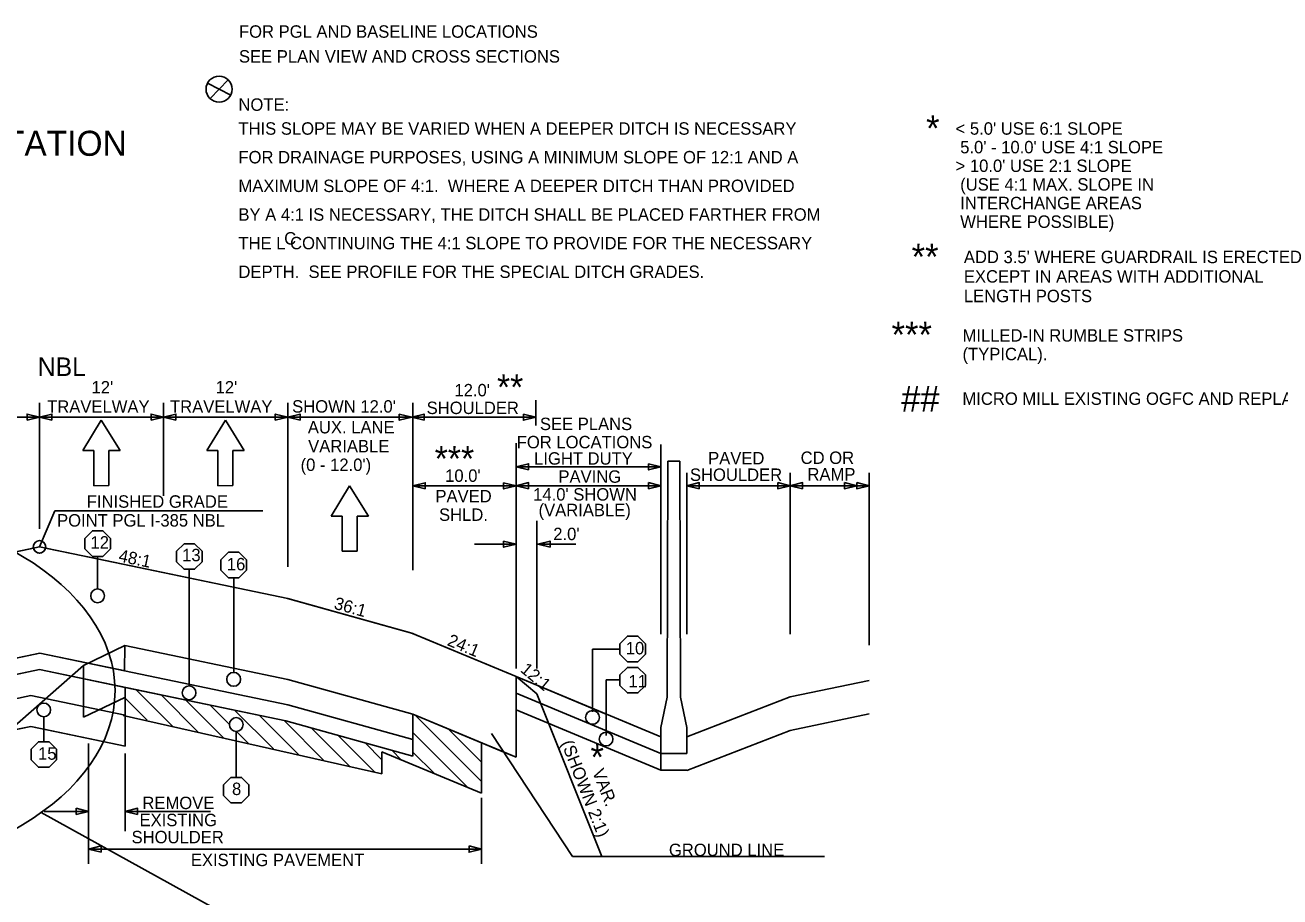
# Model space of a CAD drawing. Extents: x 4832 to 5477, y 4935 to 5220.
# Drawn here: x 5211.3 to 5332.6, y 5131.6 to 5215.9 of the extents above; entities that cross this region are included whole.
import ezdxf

# ---------------------------------------------------------------- set-up
doc = ezdxf.new("R2010")
doc.units = 0
for name, color, linetype in [('CLS_Clear_Zone', 7, 'Continuous'), ('Level 2', 7, 'Continuous'), ('RD_QTY_Milling', 7, 'Continuous'), ('RD_QTY_Miscl_1', 7, 'Continuous'), ('RD_QTY_Surf_Course', 7, 'Continuous'), ('RD_SHT_TX', 7, 'Continuous'), ('RD_SHT_Typical', 7, 'Continuous'), ('RD_TX_Misc1', 7, 'Continuous'), ('RD_TX_TypSect', 7, 'Continuous'), ('RD_XS_ExGround', 7, 'Continuous'), ('RD_XS_ExPaveRet', 7, 'Continuous'), ('RD_XS_PaveShd', 7, 'Continuous'), ('TERMINATOR', 7, 'Continuous'), ('typical_on', 7, 'Continuous')]:
    doc.layers.add(name, color=color, linetype=linetype)

# ---------------------------------------------------------------- blocks, each defined once
blk = doc.blocks.new('AH')
at = {"layer": 'TERMINATOR'}
blk.add_lwpolyline([(-6, 1.5), (0, 0), (-6, -1.5)], close=True, dxfattribs=at)

msp = doc.modelspace()

# ---------------------------------------------------------------- linework, layer by layer
at = {"layer": 'CLS_Clear_Zone'}
msp.add_line((5248.78, 5149.27), (5248.78, 5145.21), dxfattribs=at)
at = {"layer": 'Level 2'}
for p, q in [((5273.37, 5150.93), (5273.45, 5173.73)), ((5274.59, 5173.73), (5273.45, 5173.73)), ((5274.67, 5150.93), (5274.59, 5173.73)), ((5273.37, 5150.93), (5272.77, 5147.97)), ((5275.27, 5147.97), (5274.67, 5150.93)), ((5272.77, 5147.97), (5272.77, 5145.46)), ((5275.27, 5145.46), (5275.27, 5147.97)), ((5272.77, 5145.46), (5275.27, 5145.46)), ((5272.77, 5143.86), (5275.27, 5143.86))]:
    msp.add_line(p, q, dxfattribs=at)
at = {"layer": 'RD_QTY_Milling'}
for p, q in [((5220.95, 5155.91), (5220.91, 5153.45)), ((5236.69, 5152.63), (5220.95, 5155.91)), ((5220.91, 5153.45), (5236.69, 5150.16)), ((5248.78, 5149.27), (5236.69, 5152.63)), ((5258.77, 5152.9), (5258.77, 5151.3)), ((5258.77, 5151.3), (5258.77, 5149.69)), ((5272.77, 5145.46), (5258.77, 5151.3)), ((5258.77, 5151.3), (5272.77, 5145.46)), ((5236.69, 5150.16), (5248.78, 5146.81)), ((5248.78, 5146.81), (5248.78, 5149.27)), ((5258.77, 5149.69), (5272.77, 5143.86)), ((5267.48, 5149.21), (5267.48, 5149.28)), ((5272.77, 5147.07), (5267.5, 5149.27)), ((5272.77, 5145.46), (5272.77, 5147.07)), ((5272.77, 5143.86), (5272.77, 5145.46))]:
    msp.add_line(p, q, dxfattribs=at)
for points in [[(5267.48, 5149.28), (5266.14, 5149.83), (5258.77, 5152.9)], [(5267.5, 5149.27), (5267.48, 5149.21)]]:
    msp.add_lwpolyline(points, dxfattribs=at)
msp.add_circle((5231.47, 5152.64), 0.666, dxfattribs=at)
at = {"layer": 'RD_QTY_Miscl_1'}
for p, q in [((5212.74, 5155.17), (5200.74, 5152.67)), ((5220.91, 5153.45), (5212.74, 5155.17)), ((5200.79, 5151.1), (5212.69, 5153.58)), ((5212.69, 5153.58), (5200.79, 5151.1)), ((5220.99, 5151.85), (5212.69, 5153.58)), ((5236.69, 5150.16), (5220.91, 5153.45)), ((5220.99, 5149.17), (5220.99, 5151.85)), ((5200.79, 5148.76), (5211.87, 5151.07)), ((5211.87, 5151.07), (5200.79, 5148.76)), ((5211.87, 5151.07), (5220.99, 5149.17)), ((5220.99, 5149.17), (5211.87, 5151.07)), ((5248.78, 5146.81), (5236.69, 5150.16)), ((5220.99, 5146.19), (5220.99, 5149.17)), ((5236.5, 5148.62), (5248.78, 5145.21)), ((5248.78, 5145.21), (5248.78, 5146.81))]:
    msp.add_line(p, q, dxfattribs=at)
for points in [[(5212.69, 5153.58), (5220.99, 5151.85), (5236.5, 5148.62)], [(5200.79, 5145.79), (5209.76, 5147.66), (5211.87, 5148.09)], [(5211.87, 5148.09), (5213.11, 5147.83), (5220.99, 5146.19)]]:
    msp.add_lwpolyline(points, dxfattribs=at)
for centre in [(5227.16, 5151.34), (5213.11, 5149.68)]:
    msp.add_circle(centre, 0.666, dxfattribs=at)
at = {"layer": 'RD_QTY_Surf_Course'}
msp.add_line((5292.9, 5152.53), (5285.26, 5150.94), dxfattribs=at)
at = {"layer": 'RD_SHT_Typical'}
for p, q in [((5236.68, 5160.44), (5248.78, 5157.08)), ((5236.69, 5152.63), (5248.78, 5149.27)), ((5258.77, 5151.3), (5258.77, 5152.9)), ((5258.77, 5152.9), (5260.77, 5151.24)), ((5258.77, 5149.69), (5258.77, 5151.3)), ((5236.69, 5150.16), (5248.78, 5146.81)), ((5248.78, 5149.27), (5258.77, 5145.11)), ((5258.77, 5149.69), (5258.77, 5145.11)), ((5292.9, 5149.31), (5285.26, 5147.71)), ((5236.5, 5148.62), (5248.78, 5145.21)), ((5272.77, 5145.46), (5272.77, 5143.86))]:
    msp.add_line(p, q, dxfattribs=at)
at = {"layer": 'RD_TX_Misc1'}
for p, q in [((5218.67, 5177.67), (5216.89, 5174.75)), ((5220.5, 5174.76), (5218.67, 5177.67)), ((5230.67, 5177.67), (5228.89, 5174.75)), ((5232.49, 5174.76), (5230.67, 5177.67)), ((5217.95, 5174.75), (5216.89, 5174.75)), ((5217.95, 5174.75), (5217.95, 5171.35)), ((5219.4, 5174.76), (5220.5, 5174.76)), ((5219.4, 5174.76), (5219.4, 5171.36)), ((5229.94, 5174.75), (5228.89, 5174.75)), ((5229.94, 5174.75), (5229.94, 5171.35)), ((5231.4, 5174.76), (5232.49, 5174.76)), ((5231.4, 5174.76), (5231.4, 5171.36)), ((5219.4, 5171.36), (5217.95, 5171.35)), ((5231.4, 5171.36), (5229.94, 5171.35)), ((5242.67, 5171.34), (5240.89, 5168.41)), ((5244.5, 5168.42), (5242.67, 5171.34)), ((5241.95, 5168.41), (5240.89, 5168.41)), ((5241.95, 5168.41), (5241.95, 5165.01)), ((5243.4, 5168.42), (5244.5, 5168.42)), ((5243.4, 5168.42), (5243.4, 5165.01)), ((5243.4, 5165.01), (5241.95, 5165.01))]:
    msp.add_line(p, q, dxfattribs=at)
at = {"layer": 'RD_TX_TypSect'}
for p, q in [((5229.19, 5208.77), (5230.93, 5210.55)), ((5228.93, 5210.23), (5231.19, 5209.08)), ((5212.7, 5167.18), (5212.7, 5179.34)), ((5224.69, 5170.38), (5224.69, 5179.34)), ((5236.69, 5163.52), (5236.69, 5179.34)), ((5248.78, 5163.2), (5248.78, 5179.34)), ((5260.68, 5177.16), (5260.68, 5179.62)), ((5200.7, 5177.97), (5212.7, 5177.97)), ((5212.7, 5177.97), (5224.69, 5177.97)), ((5224.69, 5177.97), (5236.69, 5177.97)), ((5236.69, 5177.97), (5248.68, 5177.97)), ((5248.68, 5177.97), (5260.68, 5177.97)), ((5258.77, 5153.69), (5258.77, 5175.46)), ((5272.77, 5157.01), (5272.77, 5175.33)), ((5272.77, 5173.17), (5258.77, 5173.17)), ((5275.27, 5157.01), (5275.27, 5172.58)), ((5285.26, 5157.01), (5285.26, 5172.58)), ((5292.9, 5155.95), (5292.9, 5172.58)), ((5248.78, 5171.33), (5258.76, 5171.33)), ((5258.77, 5171.35), (5272.77, 5171.35)), ((5275.27, 5171.35), (5285.26, 5171.35)), ((5285.26, 5171.35), (5292.9, 5171.35)), ((5214.19, 5168.91), (5212.7, 5165.44)), ((5214.19, 5168.91), (5234.3, 5168.91)), ((5260.77, 5153.69), (5260.77, 5167.96)), ((5254.76, 5165.7), (5258.76, 5165.7)), ((5264.53, 5165.7), (5260.86, 5165.7)), ((5200.7, 5162.94), (5212.7, 5165.44)), ((5212.11, 5165.32), (5200.7, 5162.94)), ((5236.69, 5160.44), (5212.7, 5165.44)), ((5218.32, 5161.38), (5218.32, 5164.52)), ((5227.18, 5163.27), (5227.18, 5152.01)), ((5231.47, 5162.46), (5231.47, 5153.31)), ((5248.68, 5157.11), (5236.69, 5160.44)), ((5200.74, 5152.67), (5212.74, 5155.17)), ((5200.74, 5152.67), (5212.74, 5155.17)), ((5220.98, 5153.45), (5212.74, 5155.17)), ((5212.74, 5155.17), (5220.91, 5153.45)), ((5220.95, 5155.91), (5220.91, 5153.45)), ((5220.91, 5153.45), (5220.95, 5155.91)), ((5236.69, 5152.63), (5220.95, 5155.91)), ((5220.95, 5155.91), (5236.69, 5152.63)), ((5268.81, 5155.55), (5266.14, 5155.55)), ((5266.14, 5149.49), (5266.14, 5155.55)), ((5200.79, 5151.1), (5212.69, 5153.58)), ((5236.5, 5148.62), (5212.69, 5153.58)), ((5236.69, 5150.16), (5220.91, 5153.45)), ((5236.69, 5152.63), (5248.78, 5149.27)), ((5258.77, 5151.3), (5258.77, 5152.9)), ((5268.81, 5152.58), (5267.48, 5152.58)), ((5267.48, 5147.2), (5267.48, 5152.58)), ((5220.99, 5149.17), (5220.99, 5151.85)), ((5258.77, 5149.69), (5258.77, 5151.3)), ((5200.79, 5148.76), (5211.87, 5151.07)), ((5220.99, 5149.17), (5211.87, 5151.07)), ((5213.11, 5149.01), (5213.11, 5146.61)), ((5220.99, 5146.19), (5220.99, 5149.17)), ((5258.77, 5145.11), (5258.77, 5149.69)), ((5200.79, 5145.79), (5211.87, 5148.09)), ((5220.99, 5146.19), (5211.87, 5148.09)), ((5231.72, 5147.6), (5231.72, 5143.17)), ((5217.45, 5146.44), (5217.45, 5134.8)), ((5220.99, 5145.47), (5220.99, 5137.96)), ((5255.43, 5141.18), (5255.43, 5134.8)), ((5212.87, 5139.76), (5239.92, 5124.84)), ((5213.16, 5139.88), (5217.45, 5139.88)), ((5220.99, 5139.88), (5229.24, 5139.88)), ((5217.45, 5136.24), (5255.43, 5136.24))]:
    msp.add_line(p, q, dxfattribs=at)
for points in [[(5236.69, 5160.44), (5218.32, 5164.27), (5213.29, 5165.32)], [(5258.77, 5152.9), (5248.77, 5157.07), (5248.68, 5157.11)], [(5248.68, 5157.11), (5248.68, 5157.11)], [(5248.78, 5149.27), (5257.57, 5145.61), (5258.77, 5145.11)]]:
    msp.add_lwpolyline(points, dxfattribs=at)
for centre, radius in [((5230.06, 5209.66), 1.26), ((5212.7, 5165.44), 0.6), ((5218.32, 5160.71), 0.666), ((5218.32, 5160.71), 0.666), ((5218.32, 5160.71), 0.666), ((5231.47, 5152.64), 0.666), ((5231.47, 5152.64), 0.666), ((5227.16, 5151.34), 0.666), ((5227.16, 5151.34), 0.666), ((5213.11, 5149.68), 0.666), ((5213.11, 5149.68), 0.666), ((5231.72, 5148.27), 0.666), ((5266.15, 5148.96), 0.666), ((5267.46, 5146.87), 0.666)]:
    msp.add_circle(centre, radius, dxfattribs=at)
msp.add_arc((5212.7, 5165.44), 0.6, 191.774, 348.226, dxfattribs=at)
msp.add_ellipse((5189.51, 5151.55), major_axis=(30.49, 0), ratio=0.60143, dxfattribs=at)
at = {"layer": 'RD_XS_ExGround'}
for p, q in [((5260.77, 5151.24), (5267.06, 5135.52)), ((5256.38, 5147.41), (5264.21, 5135.52)), ((5264.21, 5135.52), (5288.58, 5135.52))]:
    msp.add_line(p, q, dxfattribs=at)
at = {"layer": 'RD_XS_ExPaveRet'}
for p, q in [((5220.95, 5155.91), (5216.95, 5153.99)), ((5216.95, 5153.99), (5209.76, 5147.66)), ((5216.95, 5153.99), (5216.95, 5148.97)), ((5222.06, 5151.63), (5225.56, 5148.13)), ((5224.45, 5151.13), (5228, 5147.57)), ((5220.95, 5150.9), (5216.95, 5148.97)), ((5220.99, 5150.81), (5223.12, 5148.68)), ((5226.83, 5150.63), (5230.44, 5147.02)), ((5229.21, 5150.14), (5231.06, 5148.29)), ((5245.79, 5143.52), (5220.8, 5149.13)), ((5231.59, 5149.64), (5235.32, 5145.91)), ((5233.97, 5149.15), (5237.76, 5145.35)), ((5249.02, 5149.17), (5255.43, 5142.76)), ((5231.75, 5147.6), (5232.88, 5146.46)), ((5236.35, 5148.65), (5240.2, 5144.8)), ((5238.95, 5147.94), (5242.65, 5144.24)), ((5248.76, 5147.55), (5254.14, 5142.17)), ((5252.25, 5147.83), (5255.43, 5144.65)), ((5241.56, 5147.21), (5245.09, 5143.69)), ((5244.17, 5146.49), (5245.79, 5144.86)), ((5255.43, 5146.53), (5255.43, 5146.53)), ((5255.43, 5146.5), (5255.43, 5141.63)), ((5255.43, 5141.63), (5245.79, 5145.65)), ((5245.79, 5143.52), (5245.79, 5145.65)), ((5246.78, 5145.76), (5247.67, 5144.87)), ((5248.77, 5145.65), (5250.9, 5143.52))]:
    msp.add_line(p, q, dxfattribs=at)
at = {"layer": 'RD_XS_PaveShd'}
for p, q in [((5248.68, 5157.11), (5258.77, 5152.9)), ((5258.77, 5152.9), (5272.77, 5147.07)), ((5258.77, 5151.3), (5272.77, 5145.46)), ((5285.26, 5150.94), (5275.27, 5147.07)), ((5258.77, 5149.69), (5272.77, 5143.86)), ((5285.26, 5147.71), (5275.27, 5143.84)), ((5272.77, 5147.07), (5272.77, 5145.46))]:
    msp.add_line(p, q, dxfattribs=at)
at = {"layer": 'typical_on'}
for points in [[(5217.09, 5166.26), (5217.09, 5165.24), (5217.81, 5164.52), (5218.83, 5164.52), (5219.56, 5165.24), (5219.56, 5166.26), (5218.83, 5166.99), (5217.81, 5166.99)], [(5225.95, 5165.01), (5225.95, 5163.99), (5226.67, 5163.27), (5227.69, 5163.27), (5228.41, 5163.99), (5228.41, 5165.01), (5227.69, 5165.73), (5226.67, 5165.73)], [(5230.24, 5164.2), (5230.24, 5163.18), (5230.96, 5162.46), (5231.98, 5162.46), (5232.7, 5163.18), (5232.7, 5164.2), (5231.98, 5164.92), (5230.96, 5164.92)], [(5268.81, 5155.06), (5268.81, 5156.08), (5269.53, 5156.81), (5270.55, 5156.81), (5271.27, 5156.08), (5271.27, 5155.06), (5270.55, 5154.34), (5269.53, 5154.34)], [(5268.81, 5152.05), (5268.81, 5153.07), (5269.53, 5153.79), (5270.55, 5153.79), (5271.27, 5153.07), (5271.27, 5152.05), (5270.55, 5151.33), (5269.53, 5151.33)], [(5211.88, 5145.89), (5211.88, 5144.87), (5212.6, 5144.15), (5213.62, 5144.15), (5214.34, 5144.87), (5214.34, 5145.89), (5213.62, 5146.61), (5212.6, 5146.61)], [(5230.49, 5142.45), (5230.49, 5141.43), (5231.21, 5140.71), (5232.23, 5140.71), (5232.95, 5141.43), (5232.95, 5142.45), (5232.23, 5143.17), (5231.21, 5143.17)]]:
    msp.add_lwpolyline(points, close=True, dxfattribs=at)

# ---------------------------------------------------------------- block references
at = {"layer": 'TERMINATOR'}
for p, xscale, yscale in [((5212.7, 5177.97), 0.2000217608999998, -0.2000217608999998), ((5224.69, 5177.97), 0.2000217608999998, -0.2000217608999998), ((5236.69, 5177.97), 0.2000217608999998, -0.2000217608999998), ((5217.45, 5139.88), 0.1999217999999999, 0.1999217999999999), ((5255.43, 5136.24), 0.1999217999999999, 0.1999217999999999)]:
    msp.add_blockref('AH', p, dxfattribs=dict(at, xscale=xscale, yscale=yscale))
for p, xscale, yscale, rotation in [((5212.7, 5177.97), 0.2000217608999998, 0.2000217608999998, 180), ((5224.69, 5177.97), 0.2000217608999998, 0.2000217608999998, 180), ((5236.69, 5177.97), 0.20002176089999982, 0.20002176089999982, 179.99858211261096), ((5248.68, 5177.97), 0.20002176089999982, 0.20002176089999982, -0.0014178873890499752), ((5248.68, 5177.97), 0.2000217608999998, 0.20002176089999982, 179.998582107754), ((5260.68, 5177.97), 0.2000217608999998, 0.20002176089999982, -0.0014178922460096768), ((5258.77, 5173.17), 0.2000217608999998, 0.20002176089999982, 179.998582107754), ((5272.77, 5173.17), 0.2000217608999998, 0.20002176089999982, -0.0014178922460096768), ((5248.78, 5171.33), 0.2000217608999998, 0.2000217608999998, 180), ((5258.76, 5171.33), 0.2000217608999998, 0.20002176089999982, -0.0014178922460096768), ((5258.77, 5171.35), 0.2000217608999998, 0.20002176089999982, 179.998582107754), ((5272.77, 5171.35), 0.2000217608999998, 0.20002176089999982, -0.0014178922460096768), ((5275.27, 5171.35), 0.2000217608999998, 0.20002176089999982, 179.998582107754), ((5285.26, 5171.35), 0.2000217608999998, 0.20002176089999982, -0.0014178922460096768), ((5285.26, 5171.35), 0.2000217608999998, 0.20002176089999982, 179.998582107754), ((5291.7, 5171.35), 0.2000217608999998, 0.20002176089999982, -0.0014178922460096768), ((5292.9, 5171.35), 0.2000217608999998, 0.20002176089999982, -0.0014178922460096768), ((5258.76, 5165.7), 0.2000217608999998, 0.20002176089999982, -0.0014178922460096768), ((5260.86, 5165.7), 0.2000217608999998, 0.20002176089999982, 179.998582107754), ((5220.99, 5139.88), 0.1999217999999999, 0.1999217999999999, 180), ((5217.45, 5136.24), 0.1999217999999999, 0.1999217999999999, 180), ((5217.45, 5136.24), 0.1999217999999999, 0.1999217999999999, 180)]:
    msp.add_blockref('AH', p, dxfattribs=dict(at, xscale=xscale, yscale=yscale, rotation=rotation))

# ---------------------------------------------------------------- texts
at = {"layer": 'RD_SHT_TX'}
msp.add_text('SOUTH CAROLINA DEPARTMENT OF TRANSPORTATION', height=2.4203, dxfattribs=at).set_placement((5133.02, 5203.22))
at = {"layer": 'RD_TX_TypSect'}
for s, height, p in [('FOR PGL AND BASELINE LOCATIONS', 1.1999, (5231.98, 5214.63)), ('SEE PLAN VIEW AND CROSS SECTIONS', 1.1999, (5231.98, 5212.23)), ('NOTE:', 1.2, (5231.93, 5207.57)), ('*', 2.5, (5298.4, 5204.63)), ('THIS SLOPE MAY BE VARIED WHEN A DEEPER DITCH IS NECESSARY', 1.1999, (5231.93, 5205.26)), ("< 5.0' USE 6:1 SLOPE", 1.1999, (5301.25, 5205.26)), (" 5.0' - 10.0' USE 4:1 SLOPE", 1.1999, (5301.25, 5203.46)), ('FOR DRAINAGE PURPOSES, USING A MINIMUM SLOPE OF 12:1 AND A', 1.1999, (5231.93, 5202.49)), ("> 10.0' USE 2:1 SLOPE", 1.1999, (5301.25, 5201.66)), ('MAXIMUM SLOPE OF 4:1.  WHERE A DEEPER DITCH THAN PROVIDED', 1.1999, (5231.93, 5199.72)), (' (USE 4:1 MAX. SLOPE IN', 1.1999, (5301.25, 5199.86)), (' INTERCHANGE AREAS', 1.1999, (5301.25, 5198.06)), ('BY A 4:1 IS NECESSARY, THE DITCH SHALL BE PLACED FARTHER FROM', 1.1999, (5231.93, 5196.95)), (' WHERE POSSIBLE)', 1.1999, (5301.25, 5196.26)), ('THE L CONTINUING THE 4:1 SLOPE TO PROVIDE FOR THE NECESSARY', 1.1999, (5231.93, 5194.19)), ('C', 1.2, (5236.35, 5194.65)), ('**', 2.5, (5297, 5192.22)), ('DEPTH.  SEE PROFILE FOR THE SPECIAL DITCH GRADES.', 1.1999, (5231.93, 5191.42)), ('***', 2.5, (5295.06, 5184.69)), ('MILLED-IN RUMBLE STRIPS', 1.1999, (5301.92, 5185.27)), ('(TYPICAL).', 1.2, (5301.92, 5183.47)), ('NBL', 1.791, (5212.53, 5181.95)), ("12'", 1.2, (5217.73, 5180.26)), ("12'", 1.2, (5229.72, 5180.26)), ('**', 2.443, (5256.92, 5179.65)), ('##', 2.5, (5295.99, 5178.51)), ('MICRO MILL EXISTING OGFC AND REPLACE WITH', 1.2001, (5301.91, 5179.16)), ('SHOULDER', 1.2, (5250.12, 5178.27)), ('SEE PLANS', 1.2, (5261.07, 5176.72)), ('VARIABLE', 1.2, (5238.67, 5174.57)), ('FOR LOCATIONS', 1.2, (5258.83, 5174.96)), ('***', 2.443, (5250.9, 5172.74)), ('LIGHT DUTY', 1.2, (5260.51, 5173.38)), ('PAVED', 1.2, (5277.33, 5173.41)), ('CD OR', 1.2, (5286.27, 5173.45)), ("(0 - 12.0')", 1.2, (5237.94, 5172.77)), ('SHOULDER', 1.2, (5275.57, 5171.81)), ('RAMP', 1.2, (5286.93, 5171.85)), ('PAVING', 1.2, (5262.86, 5171.63)), ("14.0' SHOWN", 1.2, (5260.42, 5169.91)), ('FINISHED GRADE', 1.2001, (5217.27, 5169.22)), ('(VARIABLE)', 1.2, (5260.94, 5168.4)), ('POINT PGL I-385 NBL', 1.2001, (5214.4, 5167.4)), ('12', 1.2, (5217.63, 5165.27)), ('13', 1.2, (5226.49, 5164.05)), ('16', 1.2, (5230.81, 5163.17)), ('10', 1.2, (5269.37, 5155.05)), ('11', 1.2, (5269.63, 5151.86)), ('*', 2.5, (5265.96, 5143.88)), ('15', 1.2, (5212.56, 5144.87)), ('8', 1.2, (5231.31, 5141.46)), ('REMOVE', 1.2, (5222.65, 5140.1)), ('EXISTING', 1.2, (5222.37, 5138.45)), ('SHOULDER', 1.2, (5221.6, 5136.8)), ('EXISTING PAVEMENT', 1.2, (5227.33, 5134.59))]:
    msp.add_text(s, height=height, dxfattribs=at).set_placement(p)
for s, height, rotation, p in [("ADD 3.5' WHERE GUARDRAIL IS ERECTED ", 1.1999, 360, (5302.05, 5192.85)), ('EXCEPT IN AREAS WITH ADDITIONAL ', 1.1999, 360, (5302.05, 5190.97)), ('LENGTH POSTS', 1.1999, 360, (5302.05, 5189.08)), ("12.0'", 1.2, 359.9993, (5252.81, 5179.98)), ('TRAVELWAY', 1.2, 359.9986, (5213.44, 5178.39)), ('TRAVELWAY', 1.2, 359.9986, (5225.32, 5178.39)), ("SHOWN 12.0'", 1.2, 359.9993, (5237.12, 5178.41)), ('AUX. LANE', 1.2, 0.0014, (5238.64, 5176.4)), ("10.0'", 1.2, 0.0014, (5251.91, 5171.72)), ('PAVED', 1.2, 0.0014, (5250.97, 5169.74)), ('SHLD.', 1.2, 0.0014, (5251.32, 5167.95)), ("2.0'", 1.2, 0.0014, (5262.36, 5166.09)), ('48:1', 1.2, 348.324, (5220.28, 5164.04)), ('36:1', 1.2, 344.4759, (5241.09, 5159.47)), ('24:1', 1.2, 337.3801, (5252.03, 5155.96)), ('12:1', 1.2, 320.1967, (5259.1, 5153.44)), ('(SHOWN 2:1)', 1.2, 291.3664, (5263.1, 5146.49)), ('VAR.', 1.2, 291.3664, (5266.11, 5143.72)), ('GROUND LINE', 1.2, 360, (5273.54, 5135.56))]:
    msp.add_text(s, height=height, rotation=rotation, dxfattribs=at).set_placement(p)

doc.saveas('drawing.dxf')
